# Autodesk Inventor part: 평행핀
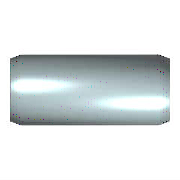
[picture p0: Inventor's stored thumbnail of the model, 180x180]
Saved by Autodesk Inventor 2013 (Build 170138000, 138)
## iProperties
IsCustomPart: 0
Created: 2009-02
Part Number: 평행핀
Material: 강, 연강
Description: 평행 핀
Document SubType Name: Modeling
Standard: KS B 1320
Designer: KYOUNG IL JANG
Standards Organization: KS
Language: ko-KR
Size Designation: B 5 x  20
Categories: <MemberInstance><Categories><Category DisplayName="조임쇠" InternalName="e4da775c-781d-43d5-af7c-5136215cf5a6" Mnemonic="FSTN"><Category DisplayName="핀" InternalNa
Density: 1 g/cm^3
Author: KYOUNG IL JANG
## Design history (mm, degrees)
sketch "스케치"
  geometry: C1 r 2.5 at (0, 0); 1 further point
  constraints: 1 centre point, 1 coincident
  dimensions: "d1" = 5 diameter of C1 (= NND)
extrude "본체" new body sketch "스케치" distance "d2" = 20 (= NLG); taper "d3" = 0 deg
chamfer "스케치2" distance "d8" = 0.8 (= PHH); stored, may be unused: angle "d9" = 15 deg (= FAWI), second distance "d12" = 0.8 (= PHH)
body "Solid1"
chamfer "모따기1" distance "d4" = 0.8 (= PHH); stored, may be unused: angle "d5" = 15 deg (= FAWI), second distance "d11" = 0.8 (= PHH)
other parameters: "NND" = 5 [user parameter; used in 1 equation term], "NLG" = 20 [user parameter; used in 1 equation term], "PHH" = 0.8 [user parameter; used in 4 equation terms], "FAWI" = 15 deg [user parameter; used in 2 equation terms], "d13" = 0, "d15" = 0, "d16" = 0, "KAH" = 0.63 [user parameter]
